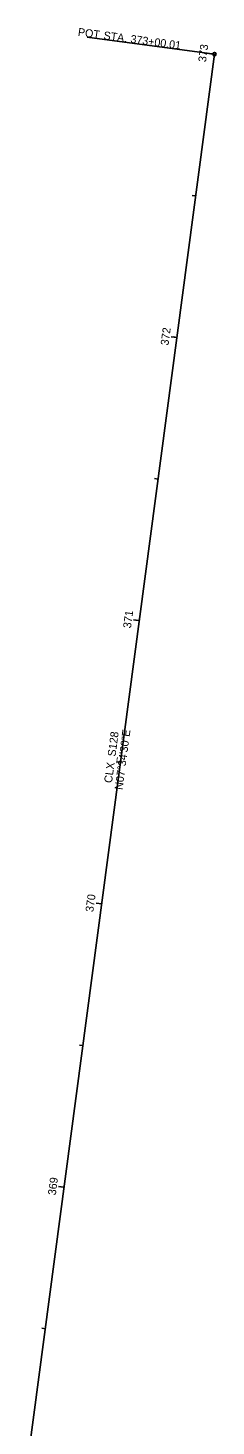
# Model space of a CAD drawing. Extents: x 1380776 to 1381901, y 503546 to 507267.
# Drawn here: x 1381834.9 to 1381900.9, y 506777.6 to 507266.9 of the extents above; entities that cross this region are included whole.
import ezdxf

# ---------------------------------------------------------------- set-up
doc = ezdxf.new("R2010")
doc.units = 0
for name, color, linetype in [('_CIVIL_CONSTRUCTION', 7, 'Continuous'), ('DR_P_Storm_Sewer', 7, 'Continuous'), ('DR_X_Storm_Sewer', 7, 'Continuous'), ('SC_Scratch1', 7, 'Continuous')]:
    doc.layers.add(name, color=color, linetype=linetype)

msp = doc.modelspace()

# ---------------------------------------------------------------- linework, layer by layer
at = {"layer": '_CIVIL_CONSTRUCTION'}
for p, q in [((1381900.34, 507257.78), (1381855.74, 507263.71)), ((1381900.34, 507257.77), (1381899.15, 507257.93)), ((1381887.16, 507158.64), (1381885.97, 507158.8)), ((1381873.98, 507059.51), (1381872.79, 507059.67)), ((1381860.8, 506960.39), (1381858.81, 506960.65)), ((1381847.61, 506861.26), (1381846.42, 506861.42))]:
    msp.add_line(p, q, dxfattribs=at)
msp.add_circle((1381900.34, 507257.78), 0.6, dxfattribs=at)
at = {"layer": 'DR_P_Storm_Sewer'}
for p, q in [((1381900.34, 507257.78), (1381855.74, 507263.71)), ((1381860.8, 506960.39), (1381858.81, 506960.65))]:
    msp.add_line(p, q, dxfattribs=at)
msp.add_circle((1381900.34, 507257.78), 0.6, dxfattribs=at)
at = {"layer": 'DR_X_Storm_Sewer'}
for p, q in [((1381900.34, 507257.78), (1381855.74, 507263.71)), ((1381900.34, 507257.77), (1381898.36, 507258.03)), ((1381893.75, 507208.2), (1381892.56, 507208.36)), ((1381887.16, 507158.64), (1381885.18, 507158.9)), ((1381880.57, 507109.08), (1381879.38, 507109.23)), ((1381873.98, 507059.51), (1381872, 507059.78)), ((1381867.39, 507009.95), (1381866.2, 507010.11)), ((1381860.8, 506960.39), (1381858.81, 506960.65)), ((1381854.21, 506910.82), (1381853.02, 506910.98)), ((1381847.61, 506861.26), (1381845.63, 506861.52)), ((1381841.02, 506811.69), (1381839.83, 506811.85))]:
    msp.add_line(p, q, dxfattribs=at)
msp.add_circle((1381900.34, 507257.78), 0.6, dxfattribs=at)
at = {"layer": 'SC_Scratch1'}
msp.add_line((1381834.89, 506765.61), (1381900.34, 507257.78), dxfattribs=at)

# ---------------------------------------------------------------- texts
at = {"layer": '_CIVIL_CONSTRUCTION'}
for s, rotation, p in [('POT', 352.4251, (1381852.32, 507264.21)), (' STA. ', 352.4251, (1381860.29, 507263.15)), ('373+00.01', 352.4251, (1381870.78, 507261.76)), ('CLX_S128', 82.4251, (1381864.39, 507002.56)), ('N07°34\'30"E', 82.4251, (1381868.1, 507000.17)), ('370', 82.4251, (1381857.84, 506957.4))]:
    msp.add_text(s, height=2.8, rotation=rotation, dxfattribs=at).set_placement(p)
at = {"layer": 'DR_P_Storm_Sewer'}
for s, rotation, p in [('POT', 352.4251, (1381852.32, 507264.21)), (' STA. ', 352.4251, (1381860.29, 507263.15)), ('373+00.01', 352.4251, (1381870.78, 507261.76)), ('CLX_S128', 82.4251, (1381864.39, 507002.56)), ('N07°34\'30"E', 82.4251, (1381868.1, 507000.17)), ('370', 82.4251, (1381857.84, 506957.4))]:
    msp.add_text(s, height=2.8, rotation=rotation, dxfattribs=at).set_placement(p)
at = {"layer": 'DR_X_Storm_Sewer'}
for s, rotation, p in [('POT', 352.4251, (1381852.32, 507264.21)), (' STA. ', 352.4251, (1381860.29, 507263.15)), ('373+00.01', 352.4251, (1381870.78, 507261.76)), ('373', 82.4251, (1381897.39, 507254.86)), ('372', 82.4251, (1381884.21, 507155.72)), ('371', 82.4251, (1381871.04, 507056.72)), ('CLX_S128', 82.4251, (1381864.39, 507002.56)), ('N07°34\'30"E', 82.4251, (1381868.1, 507000.17)), ('370', 82.4251, (1381857.84, 506957.4)), ('369', 82.4251, (1381844.66, 506858.3))]:
    msp.add_text(s, height=2.8, rotation=rotation, dxfattribs=at).set_placement(p)

doc.saveas('drawing.dxf')
